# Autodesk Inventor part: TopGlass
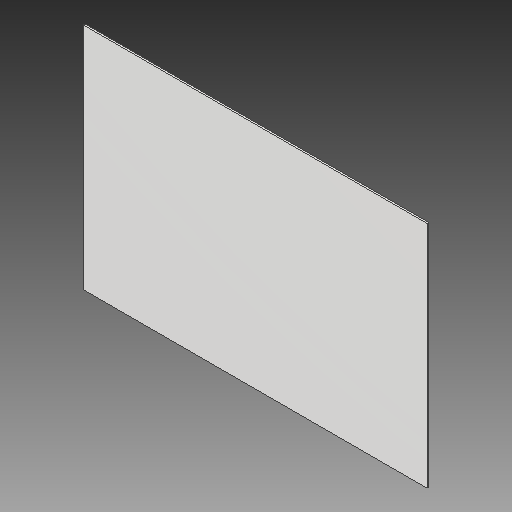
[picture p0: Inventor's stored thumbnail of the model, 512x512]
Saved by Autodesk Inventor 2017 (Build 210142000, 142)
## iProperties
Created: 2017-05
Part Number: TopGlass
Material: Generic
Document SubType Name: Modeling
Designer: Savy
Density: 1 g/cm^3
Appearance: Default
Mass: 2653.31 g
Surface Area: 11293.4 cm^2
Volume: 2653.31 cm^3
Author: Savy
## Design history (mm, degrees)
feature "SOLID1"
body "Solid1"
